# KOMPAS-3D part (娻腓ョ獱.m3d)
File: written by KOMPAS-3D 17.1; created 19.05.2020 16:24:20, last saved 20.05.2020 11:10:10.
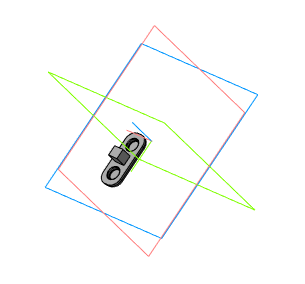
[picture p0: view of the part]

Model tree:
1. Эскиз:1
2. Операция выдавливания:1
     Расстояние 1 = 1.9
3. Эскиз:3
4. Вырезать элемент выдавливания:2
     Расстояние 1 = 1; Угол 1 = 5
5. Эскиз:4
6. Элемент выдавливания:1
     Расстояние 1 = 3.9
7. Скругление:1
     Радиус = 3
8. Скругление:5
     Радиус = 0.2
9. Скругление:6
     Радиус = 1.2
10. Зеркальный массив:4
11. Экземпляр ( 1 )
12. Экземпляр ( 2 )  (with: Операция выдавливания:1, Вырезать элемент выдавливания:2, Элемент выдавливания:1, Скругление:1, Скругление:5, Скругление:6)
